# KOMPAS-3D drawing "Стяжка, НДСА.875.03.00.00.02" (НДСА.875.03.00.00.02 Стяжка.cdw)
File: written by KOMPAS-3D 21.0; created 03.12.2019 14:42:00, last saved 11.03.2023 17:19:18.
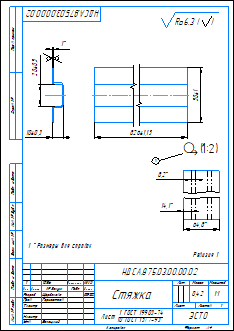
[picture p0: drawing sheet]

Sheet 1: A4, portrait

Document properties: Автор: 111; Организация: Эсто-вакуум; Полное имя файла: C:\Users\s.pischagina\Desktop\PLM\НДСА.875.03.00.00.02 Стяжка.cdw; Знак неуказанной шероховатости: 4; Параметр неуказанной шероховатости: Ra6.3; 250117810646: <item xmlns="http://appius.ru/pdm" xmlns:xs="http://www.w3.org/2001/XMLSchema" xmlns:xsi="http://www.w3.org/2001/XMLSchema-instance" xsi:type="item">  <element xmlns:d2p1="http://v8.1c.ru/8.1/data/enterprise/current-config" xsi:type="d2p1:CatalogRef.aps_Элемен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; Масса: 0.4226; 354593324382: <item xmlns="http://appius.ru/pdm" xmlns:xs="http://www.w3.org/2001/XMLSchema" xmlns:xsi="http://www.w3.org/2001/XMLSchema-instance" xsi:type="item">  <element xmlns:d2p1="http://v8.1c.ru/8.1/data/enterprise/current-config" xsi:type="d2p1:CatalogRef.aps_Элемен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; PLM_CDWXDTO: <item xmlns="http://appius.ru/pdm" xmlns:xs="http://www.w3.org/2001/XMLSchema" xmlns:xsi="http://www.w3.org/2001/XMLSchema-instance" xsi:type="item">  <element xmlns:d2p1="http://v8.1c.ru/8.1/data/enterprise/current-config" xsi:type="d2p1:CatalogRef.aps_Элемен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; 248902166555: <item xmlns="http://appius.ru/pdm" xmlns:xs="http://www.w3.org/2001/XMLSchema" xmlns:xsi="http://www.w3.org/2001/XMLSchema-instance" xsi:type="item">  <element xmlns:d2p1="http://v8.1c.ru/8.1/data/enterprise/current-config" xsi:type="d2p1:CatalogRef.aps_Элемен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; 248902166655: <item xmlns="http://appius.ru/pdm" xmlns:xs="http://www.w3.org/2001/XMLSchema" xmlns:xsi="http://www.w3.org/2001/XMLSchema-instance" xsi:type="item">  <element xmlns:d2p1="http://v8.1c.ru/8.1/data/enterprise/current-config" xsi:type="d2p1:CatalogRef.aps_Элемен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; 248902166755: <item xmlns="http://appius.ru/pdm" xmlns:xs="http://www.w3.org/2001/XMLSchema" xmlns:xsi="http://www.w3.org/2001/XMLSchema-instance" xsi:type="item">  <element xmlns:d2p1="http://v8.1c.ru/8.1/data/enterprise/current-config" xsi:type="d2p1:CatalogRef.aps_Элемен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; 354593324782: <item xmlns="http://appius.ru/pdm" xmlns:xs="http://www.w3.org/2001/XMLSchema" xmlns:xsi="http://www.w3.org/2001/XMLSchema-instance" xsi:type="item">  <element xmlns:d2p1="http://v8.1c.ru/8.1/data/enterprise/current-config" xsi:type="d2p1:CatalogRef.aps_Элемен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; 354593324882: <item xmlns="http://appius.ru/pdm" xmlns:xs="http://www.w3.org/2001/XMLSchema" xmlns:xsi="http://www.w3.org/2001/XMLSchema-instance" xsi:type="item">  <element xmlns:d2p1="http://v8.1c.ru/8.1/data/enterprise/current-config" xsi:type="d2p1:CatalogRef.aps_Элемен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; 354593324982: <item xmlns="http://appius.ru/pdm" xmlns:xs="http://www.w3.org/2001/XMLSchema" xmlns:xsi="http://www.w3.org/2001/XMLSchema-instance" xsi:type="item">  <element xmlns:d2p1="http://v8.1c.ru/8.1/data/enterprise/current-config" xsi:type="d2p1:CatalogRef.aps_Элемен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; PDM_DOCXDTO: <item xmlns="http://appius.ru/pdm" xmlns:xs="http://www.w3.org/2001/XMLSchema" xmlns:xsi="http://www.w3.org/2001/XMLSchema-instance" xsi:type="item">  <element xmlns:d2p1="http://v8.1c.ru/8.1/data/enterprise/current-config" xsi:type="d2p1:CatalogRef.aps_Элемен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; PDM_ITEMXDTO: <item xmlns="http://appius.ru/pdm" xmlns:xs="http://www.w3.org/2001/XMLSchema" xmlns:xsi="http://www.w3.org/2001/XMLSchema-instance" xsi:type="item">  <element xmlns:d2p1="http://v8.1c.ru/8.1/data/enterprise/current-config" xsi:type="d2p1:CatalogRef.aps_Элемен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; PDM_DRAWINGXDTO: <item xmlns="http://appius.ru/pdm" xmlns:xs="http://www.w3.org/2001/XMLSchema" xmlns:xsi="http://www.w3.org/2001/XMLSchema-instance" xsi:type="item">  <element xmlns:d2p1="http://v8.1c.ru/8.1/data/enterprise/current-config" xsi:type="d2p1:CatalogRef.aps_Элемен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

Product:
- Part/product: Стяжка  | designation НДСА.875.03.00.00.02
    Масса: 0.4226
    additional columns: <item xmlns="http://appius.ru/pdm" xmlns:xs="http://www.w3.org/2001/XMLSchema" x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; <item xmlns="http://appius.ru/pdm" xmlns:xs="http://www.w3.org/2001/XMLSchema" x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; <item xmlns="http://appius.ru/pdm" xmlns:xs="http://www.w3.org/2001/XMLSchema" x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; <item xmlns="http://appius.ru/pdm" xmlns:xs="http://www.w3.org/2001/XMLSchema" x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; <item xmlns="http://appius.ru/pdm" xmlns:xs="http://www.w3.org/2001/XMLSchema" x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; <item xmlns="http://appius.ru/pdm" xmlns:xs="http://www.w3.org/2001/XMLSchema" x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; <item xmlns="http://appius.ru/pdm" xmlns:xs="http://www.w3.org/2001/XMLSchema" x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; <item xmlns="http://appius.ru/pdm" xmlns:xs="http://www.w3.org/2001/XMLSchema" x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
    source file: НДСА.875.03.00.00.02 Стяжка.cdw

Title block, sheet 1: Наименование: Стяжка; designation: НДСА.875.03.00.00.02; Материал: Лист  1 ГОСТ 19903-74 10 ГОСТ 1577-93; Масса: 0,42; Количество листов документа: 1; organisation: ЭСТО; Форматы листов документа: A4; stored path: C:\Users\Конструктор 1\Desktop\НДСА.808.00.00.00.00 Рама с заглушками\НДСА.808.02.00.00.03 Стяжка.cdw; Разработал: Щербакова; Проверил: Горностаев; Утвердил: Белецкий; Разработал, date: 07.09.2022

Views: Вид 1, Спереди, Проекционный вид 2, Вид 3, Развертка
Referenced files in C:\Users\Конструктор 1\Desktop\НДСА.808.00.00.00.00 Рама с заглушками\: НДСА.808.02.00.00.03 Стяжка.m3d
Referenced files in C:\Users\cherbakova\Desktop\PLM\: НДСА.875.03.00.00.02 Стяжка.m3d
Referenced files in C:\Users\s.pischagina\Desktop\PLM\: НДСА.875.03.00.00.02 Стяжка.m3d
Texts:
  Ревизия 1.
  Линейный размер
  Ra6.3
  Ra6.3 ( )
  Пищагина
  НДСА.875.03.00.00.02 Стяжка
Dimensions and other numbers on the sheet: 10±0,3; 20; 1; 826±1,15; 50±1; 14,1; 8,2; 64,8; 1:1; 0,42; 07.09.2022; 1256; 11.03.23

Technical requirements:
  *Размеры для справок.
